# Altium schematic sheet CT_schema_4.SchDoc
size 360 x 340 mm
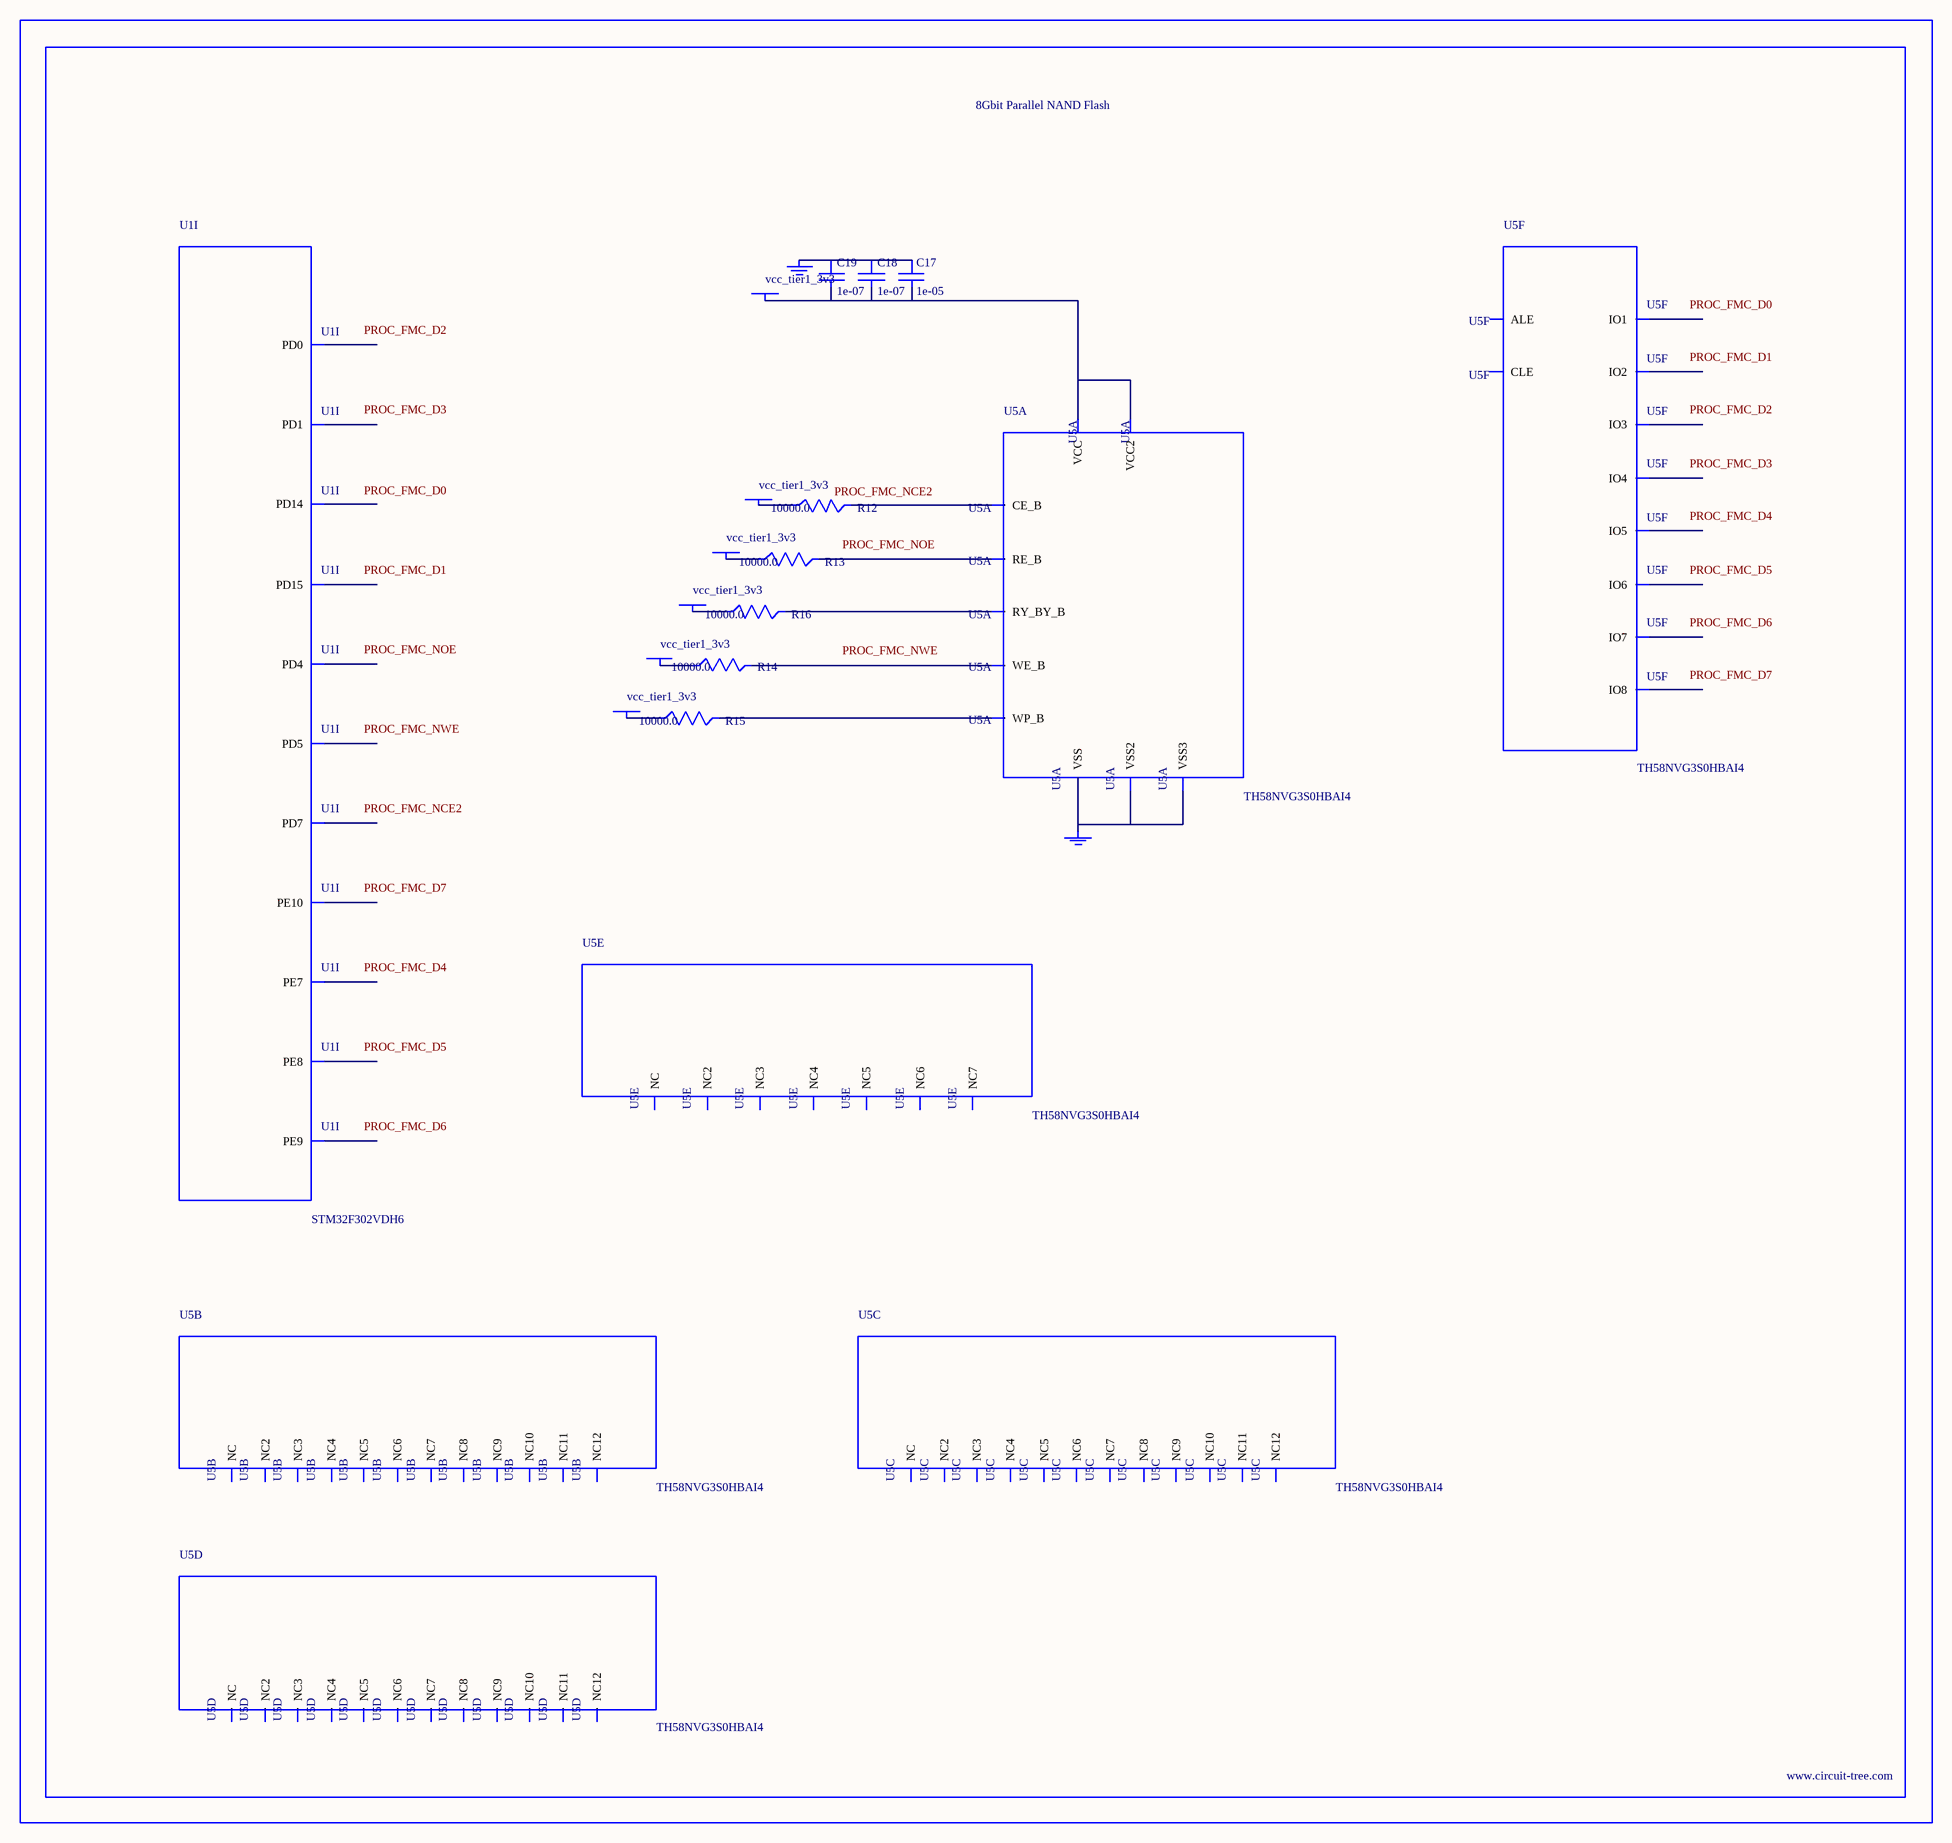
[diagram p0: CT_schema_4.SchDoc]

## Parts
BORDER3  (no value)
C17  1e-05  [C0805]
C18  1e-07  [C0402]
C19  1e-07  [C0402]
GND_INSTANCE_3_0  (no value)
GND_INSTANCE_3_1  (no value)
POWER_INSTANCE_3_0  vcc_tier1_3v3
POWER_INSTANCE_3_1  vcc_tier1_3v3
POWER_INSTANCE_3_2  vcc_tier1_3v3
POWER_INSTANCE_3_3  vcc_tier1_3v3
POWER_INSTANCE_3_4  vcc_tier1_3v3
POWER_INSTANCE_3_5  vcc_tier1_3v3
R12  10000.0  [R0603]
R13  10000.0  [R0603]
R14  10000.0  [R0603]
R15  10000.0  [R0603]
R16  10000.0  [R0603]
U1  STM32F302VDH6  [UFBGA100]  (part I of 9)
U5  TH58NVG3S0HBAI4  [TH58NVG3S0HBAI4]  (parts A,B,C,D,E,F of 6)

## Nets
NetC17_1: C17.1 C18.1 C19.1 GND_INSTANCE_3_0.0(GND)
NetC17_2: C17.2 C18.2 C19.2 POWER_INSTANCE_3_5.0(PWR) U5.H8(VCC) U5.J6(VCC2)
NetGND_INSTANCE_3_1_0: GND_INSTANCE_3_1.0(GND) U5.C5(VSS) U5.K3(VSS2) U5.K8(VSS3)
NetPOWER_INSTANCE_3_0_0: POWER_INSTANCE_3_0.0(PWR) R12.1
NetPOWER_INSTANCE_3_1_0: POWER_INSTANCE_3_1.0(PWR) R13.1
NetPOWER_INSTANCE_3_2_0: POWER_INSTANCE_3_2.0(PWR) R14.1
NetPOWER_INSTANCE_3_3_0: POWER_INSTANCE_3_3.0(PWR) R15.1
NetPOWER_INSTANCE_3_4_0: POWER_INSTANCE_3_4.0(PWR) R16.1
NetR12_2: R12.2 U5.C6(CE_B)
NetR13_2: R13.2 U5.D4(RE_B)
NetR14_2: R14.2 U5.C7(WE_B)
NetR15_2: R15.2 U5.C3(WP_B)
NetR16_2: R16.2 U5.C8(RY_BY_B)

Not connected (* = marked no-connect by the designer): U1 A5(PD7) A6(PD5) B7(PD4) B9(PD1) C9(PD0) H10(PD15) H11(PD14) L7(PE8) L8(PE10) M7(PE7) M8(PE9); U5 A1(NC) A2(NC3) A9(NC4) A10(NC2) B1(NC5) B9(NC7) B10(NC6) C4(ALE) D3(NC8) D5(CLE) D6(NC9) D7(NC10) D8(NC11) E3(NC12) E4(NC) E5(NC2) E6(NC3) E7(NC4) E8(NC5) F3(NC6) F4(NC7) F5(NC8) F6(NC9) F7(NC10) F8(NC11) G3(NC12) G4(NC) G5(NC2) G6(NC3) G7(NC4) G8(NC5) H3(NC6) H4(IO1) H5(NC7) H6(NC8) H7(NC9) J3(NC10) J4(IO2) J5(NC11) J7(IO6) J8(IO8) K4(IO3) K5(IO4) K6(IO5) K7(IO7) L1(NC12) L2(NC2) L9(NC3) L10(NC) M1(NC4) M2(NC6) M9(NC7) M10(NC5)

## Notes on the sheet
- Labels drawn without touching a wire or pin: PROC_FMC_D0, PROC_FMC_D1, PROC_FMC_D2, PROC_FMC_D3, PROC_FMC_D4, PROC_FMC_D5, PROC_FMC_D6, PROC_FMC_D7, PROC_FMC_NCE2, PROC_FMC_NOE, PROC_FMC_NWE

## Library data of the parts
BORDER3 = BORDER_PAGE3
C17 = C0805C106K8RACTU
C18 C19 = C0402C104K3RACTU
GND_INSTANCE_3_0 GND_INSTANCE_3_1 = GND
POWER_INSTANCE_3_0-POWER_INSTANCE_3_5 = PWR
R12-R16 = RC0603JR-0710KL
